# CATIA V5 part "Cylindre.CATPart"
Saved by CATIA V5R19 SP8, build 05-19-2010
Part number: Cylindre
Publications: "Rayon_cylindre"
Bounding box of the stored display mesh (mm): x 0 to 100, y -9.942 to 9.942, z -9.942 to 9.942
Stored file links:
  F:\! CONCEPTION\PROJET\Mécanisme 11\CAO\Cylindre.CATPart
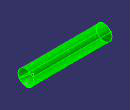
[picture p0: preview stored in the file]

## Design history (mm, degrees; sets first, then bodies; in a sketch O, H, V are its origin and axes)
Parameters
  Rayon_cylindre = 10 mm
Body1 (main body)
  Sketch1 on xy-plane, origin (0, 0, 0), H (1, 0, 0), V (0, 1, 0)
    point P1 (0, 0)
    line L1 (0, 0) -> (0, 10)
    line L2 (0, 10) -> (100, 10)
    point P3 (100, 10)
    line L3 (100, 10) -> (90, 0)
    point P4 (90, 0)
    line L4 (90, 0) -> (0, 0)
    distance L4 L2 = 10 {= Rayon_cylindre}
    distance P3 P4 H = 10 {= Rayon_cylindre}
    distance L1 P4 = 90
    coincidence: P1 H, P4 H, L1 V
    vertical: L1 V
    horizontal: L2 H, L4 H
  Shaft1: profile Sketch1, axis Sketch1.H, angle 360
